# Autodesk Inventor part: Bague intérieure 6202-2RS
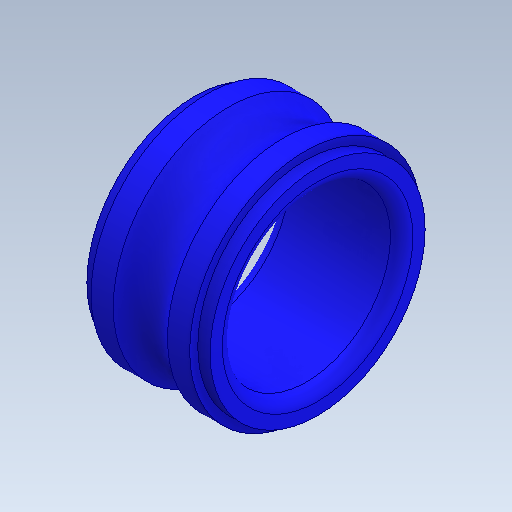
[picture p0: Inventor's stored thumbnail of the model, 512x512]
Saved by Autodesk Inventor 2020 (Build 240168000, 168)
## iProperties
Created: 2003-06
Part Number: Bague intérieure 6202-2RS
Material: Générique
Document SubType Name: Modeling
Designer: Bruno
Density: 1 g/cm^3
Appearance: Par défaut
Author: Bruno
Sending System: SolidWorks 2011
Last Author: frederic
Last Saved: 2012-02-20
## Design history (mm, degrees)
feature "Base-Révolution"
node "Solide1"
